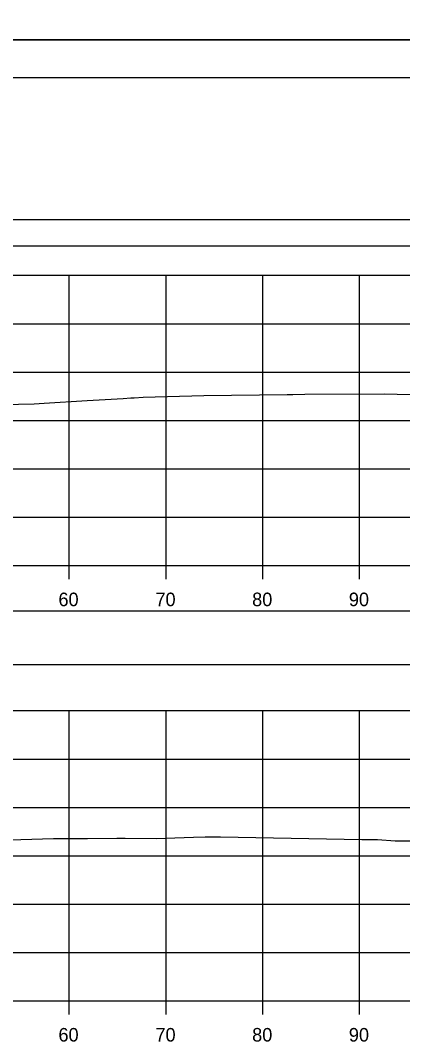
# Model space of a CAD drawing. Extents: x 1369627 to 1374022, y 380035 to 398173.
# Drawn here: x 1372153.5 to 1372193, y 383561.8 to 383667.5 of the extents above; entities that cross this region are included whole.
import ezdxf

# ---------------------------------------------------------------- set-up
doc = ezdxf.new("R2010")
doc.units = 0
for name, color, linetype in [('Default', 7, 'Continuous'), ('R_Axis', 7, 'Continuous'), ('R_Axis Annot', 7, 'Continuous'), ('R_Border', 7, 'Continuous'), ('R_Exist Surface', 7, 'Continuous'), ('R_Grid', 7, 'Continuous'), ('R_No Plot', 7, 'Continuous')]:
    doc.layers.add(name, color=color, linetype=linetype)

msp = doc.modelspace()

# ---------------------------------------------------------------- linework, layer by layer
at = {"layer": 'Default'}
for points in [[(1371948.53, 383644.2), (1372248.53, 383644.2), (1372248.53, 383646.91), (1371948.53, 383646.91)], [(1371948.53, 383600.94), (1372248.53, 383600.94), (1372248.53, 383606.46), (1371948.53, 383606.46)]]:
    msp.add_lwpolyline(points, close=True, dxfattribs=at)
at = {"layer": 'R_Axis'}
for p, q in [((1371948.53, 383611.17), (1372248.53, 383611.17)), ((1372158.53, 383609.77), (1372158.53, 383611.17)), ((1372168.53, 383609.77), (1372168.53, 383611.17)), ((1372178.53, 383609.77), (1372178.53, 383611.17)), ((1372188.53, 383609.77), (1372188.53, 383611.17)), ((1371948.53, 383566.17), (1372248.53, 383566.17)), ((1372158.53, 383564.77), (1372158.53, 383566.17)), ((1372168.53, 383564.77), (1372168.53, 383566.17)), ((1372178.53, 383564.77), (1372178.53, 383566.17)), ((1372188.53, 383564.77), (1372188.53, 383566.17))]:
    msp.add_line(p, q, dxfattribs=at)
at = {"layer": 'R_Border'}
msp.add_line((1371940.53, 383661.63), (1372256.71, 383661.63), dxfattribs=at)
at = {"layer": 'R_Exist Surface'}
for points in [[(1372145.22, 383627.68), (1372154.89, 383627.87), (1372155.93, 383627.95), (1372160.37, 383628.22), (1372164.11, 383628.45), (1372164.91, 383628.5), (1372165.24, 383628.52), (1372166.16, 383628.56), (1372172.43, 383628.74), (1372181.05, 383628.85), (1372181.63, 383628.86), (1372182.88, 383628.9), (1372191.1, 383628.91), (1372197.88, 383628.76), (1372202.49, 383628.66), (1372210.71, 383628.47), (1372213.45, 383628.34), (1372226.1, 383627.78), (1372230.83, 383627.61), (1372231.87, 383627.55)], [(1372147.85, 383582.67), (1372156.91, 383582.94), (1372160.4, 383582.94), (1372163.45, 383583), (1372164.3, 383582.98), (1372167.53, 383582.96), (1372171.37, 383583.08), (1372172.59, 383583.12), (1372174.15, 383583.14), (1372188.77, 383582.87), (1372190.41, 383582.85), (1372192.21, 383582.73), (1372196.16, 383582.73), (1372200.32, 383582.9), (1372204.01, 383582.74), (1372210.09, 383582.71), (1372212.88, 383582.63), (1372215.49, 383582.61), (1372218.23, 383582.48), (1372220.29, 383582.58), (1372223.09, 383582.49), (1372224.74, 383582.29), (1372226.74, 383582.24)]]:
    msp.add_lwpolyline(points, dxfattribs=at)
at = {"layer": 'R_Grid'}
for p, q in [((1371948.53, 383641.17), (1372248.53, 383641.17)), ((1372158.53, 383611.17), (1372158.53, 383641.17)), ((1372168.53, 383611.17), (1372168.53, 383641.17)), ((1372178.53, 383611.17), (1372178.53, 383641.17)), ((1372188.53, 383611.17), (1372188.53, 383641.17)), ((1371948.53, 383636.17), (1372248.53, 383636.17)), ((1371948.53, 383631.17), (1372248.53, 383631.17)), ((1371948.53, 383626.17), (1372248.53, 383626.17)), ((1371948.53, 383621.17), (1372248.53, 383621.17)), ((1371948.53, 383616.17), (1372248.53, 383616.17)), ((1371948.53, 383611.17), (1372248.53, 383611.17)), ((1371948.53, 383596.17), (1372248.53, 383596.17)), ((1372158.53, 383566.17), (1372158.53, 383596.17)), ((1372168.53, 383566.17), (1372168.53, 383596.17)), ((1372178.53, 383566.17), (1372178.53, 383596.17)), ((1372188.53, 383566.17), (1372188.53, 383596.17)), ((1371948.53, 383591.17), (1372248.53, 383591.17)), ((1371948.53, 383586.17), (1372248.53, 383586.17)), ((1371948.53, 383581.17), (1372248.53, 383581.17)), ((1371948.53, 383576.17), (1372248.53, 383576.17)), ((1371948.53, 383571.17), (1372248.53, 383571.17)), ((1371948.53, 383566.17), (1372248.53, 383566.17))]:
    msp.add_line(p, q, dxfattribs=at)
at = {"layer": 'R_No Plot'}
msp.add_line((1371928.13, 383665.52), (1372261.46, 383665.52), dxfattribs=at)
msp.add_line((1371928.13, 383665.52), (1372261.46, 383665.52), dxfattribs=at)
for points in [[(1371928.12, 383878.85), (1372261.46, 383878.85), (1372261.46, 383665.52), (1371928.12, 383665.52)], [(1371928.12, 383665.52), (1372261.46, 383665.52), (1372261.46, 383452.18), (1371928.12, 383452.18)], [(1372174.45, 383661.63), (1372194.07, 383661.63), (1372194.07, 383651.75), (1372210.18, 383651.75), (1372233.38, 383651.75), (1372233.38, 383619.08), (1372256.59, 383619.08), (1372256.71, 383456.17), (1371940.53, 383456.17), (1371940.53, 383661.63)]]:
    msp.add_lwpolyline(points, close=True, dxfattribs=at)

# ---------------------------------------------------------------- texts
at = {"layer": 'R_Axis Annot'}
for s, p in [('60', (1372157.41, 383606.97)), ('70', (1372167.44, 383606.97)), ('80', (1372177.44, 383606.97)), ('90', (1372187.44, 383606.97)), ('60', (1372157.41, 383561.97)), ('70', (1372167.44, 383561.97)), ('80', (1372177.44, 383561.97)), ('90', (1372187.44, 383561.97))]:
    msp.add_text(s, height=1.4, dxfattribs=at).set_placement(p)

doc.saveas('drawing.dxf')
